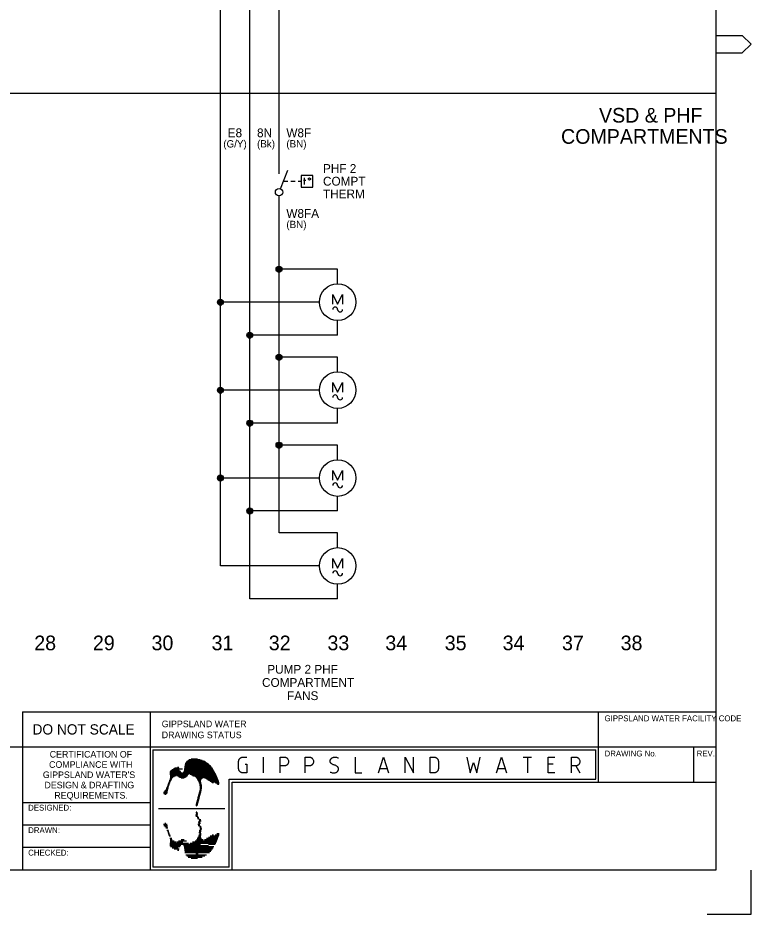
# Model space of a CAD drawing. Extents: x 0 to 841, y 0 to 594.
# Drawn here: x 590.9 to 841, y 0 to 305.7 of the extents above; entities that cross this region are included whole.
import ezdxf

# ---------------------------------------------------------------- set-up
doc = ezdxf.new("R2010")
doc.units = 0
for name, color, linetype in [('A1BORDER', 7, 'Continuous'), ('Level 1', 7, 'Continuous'), ('Level 10', 7, 'Continuous')]:
    doc.layers.add(name, color=color, linetype=linetype)

msp = doc.modelspace()

# ---------------------------------------------------------------- linework, layer by layer
at = {"layer": 'A1BORDER'}
for p, q in [((829, 581), (829, 15)), ((829, 299.76), (838, 299.76)), ((838, 299.76), (841, 296.76)), ((838, 293.76), (841, 296.76)), ((829, 293.76), (838, 293.76)), ((592.5, 69), (592.5, 15)), ((592.5, 69), (829, 69)), ((636, 69), (636, 15)), ((789, 45), (789, 69)), ((28, 57), (829, 57)), ((637, 56), (788, 56)), ((637, 56), (637, 16)), ((788, 46), (788, 56)), ((821.5, 45), (821.5, 57)), ((648.53, 52.12), (654.64, 52.12)), ((648.74, 52.32), (654.24, 52.32)), ((649.02, 52.52), (653.76, 52.52)), ((649.39, 52.72), (653.15, 52.72)), ((650.01, 52.92), (652.2, 52.92)), ((643.04, 48.92), (646.16, 48.92)), ((643.26, 49.12), (645.9, 49.12)), ((643.54, 49.32), (645.57, 49.32)), ((643.85, 49.52), (647.09, 49.52)), ((644.18, 49.72), (645.89, 49.72)), ((644.54, 49.92), (645.36, 49.92)), ((645.37, 50.12), (645.86, 50.12)), ((647.61, 48.92), (657.8, 48.92)), ((647.63, 49.12), (657.68, 49.12)), ((647.66, 49.32), (657.57, 49.32)), ((647.69, 49.52), (657.44, 49.52)), ((647.71, 49.72), (657.31, 49.72)), ((647.75, 49.92), (657.17, 49.92)), ((647.78, 50.12), (657.02, 50.12)), ((647.81, 50.32), (656.86, 50.32)), ((647.85, 50.52), (656.69, 50.52)), ((647.88, 50.72), (656.5, 50.72)), ((647.91, 50.92), (656.3, 50.92)), ((647.96, 51.12), (656.08, 51.12)), ((648.03, 51.32), (655.85, 51.32)), ((648.12, 51.52), (655.59, 51.52)), ((648.23, 51.72), (655.31, 51.72)), ((648.37, 51.92), (655, 51.92)), ((642.72, 45.92), (643.3, 45.92)), ((642.73, 48.12), (658.25, 48.12)), ((642.74, 47.92), (658.35, 47.92)), ((642.75, 48.32), (646.79, 48.32)), ((642.79, 47.72), (649.08, 47.72)), ((642.79, 46.12), (643.4, 46.12)), ((642.81, 48.52), (646.55, 48.52)), ((642.83, 47.52), (648.95, 47.52)), ((642.84, 46.32), (643.5, 46.32)), ((642.85, 47.31), (644.88, 47.31)), ((642.87, 47.12), (644.57, 47.12)), ((642.87, 46.52), (643.6, 46.52)), ((642.88, 46.92), (644.23, 46.92)), ((642.88, 46.72), (643.83, 46.72)), ((642.9, 48.72), (646.37, 48.72)), ((645.14, 47.31), (648.83, 47.31)), ((645.49, 47.12), (648.67, 47.12)), ((645.76, 46.92), (648.42, 46.92)), ((646.05, 46.72), (648.11, 46.72)), ((646.62, 46.52), (647.67, 46.52)), ((647.19, 48.32), (658.14, 48.32)), ((647.42, 48.52), (658.03, 48.52)), ((647.54, 48.72), (657.92, 48.72)), ((649.72, 47.72), (658.45, 47.72)), ((650.12, 47.52), (658.55, 47.52)), ((650.48, 47.31), (658.64, 47.31)), ((650.87, 47.12), (658.73, 47.12)), ((651.36, 46.92), (658.82, 46.92)), ((651.76, 46.72), (658.9, 46.72)), ((651.88, 46.52), (654.15, 46.52)), ((651.99, 46.32), (653.71, 46.32)), ((652.1, 46.12), (653.52, 46.12)), ((652.2, 45.92), (653.4, 45.92)), ((654.57, 46.52), (658.99, 46.52)), ((655, 46.32), (659.07, 46.32)), ((655.31, 46.12), (659.14, 46.12)), ((655.62, 45.92), (659.22, 45.92)), ((663, 46), (788, 46)), ((663, 16), (663, 46)), ((641.55, 42.92), (642.2, 42.92)), ((641.64, 43.12), (642.25, 43.12)), ((641.73, 43.32), (642.3, 43.32)), ((641.82, 43.51), (642.35, 43.51)), ((641.91, 43.72), (642.41, 43.72)), ((641.99, 43.92), (642.48, 43.92)), ((642.06, 44.12), (642.55, 44.12)), ((642.13, 44.32), (642.62, 44.32)), ((642.21, 44.52), (642.69, 44.52)), ((642.28, 44.72), (642.76, 44.72)), ((642.35, 44.92), (642.83, 44.92)), ((642.43, 45.12), (642.9, 45.12)), ((642.5, 45.32), (643, 45.32)), ((642.57, 45.52), (643.1, 45.52)), ((642.65, 45.72), (643.2, 45.72)), ((652.31, 45.72), (653.33, 45.72)), ((652.41, 45.52), (653.31, 45.52)), ((652.5, 45.32), (653.34, 45.32)), ((652.6, 45.12), (653.38, 45.12)), ((652.69, 44.92), (653.41, 44.92)), ((652.78, 44.72), (653.44, 44.72)), ((652.83, 44.52), (653.48, 44.52)), ((652.86, 44.32), (653.53, 44.32)), ((652.89, 44.12), (653.57, 44.12)), ((652.91, 43.92), (653.62, 43.92)), ((652.94, 43.72), (653.67, 43.72)), ((652.97, 43.51), (653.71, 43.51)), ((653, 43.32), (653.69, 43.32)), ((653.02, 43.12), (653.67, 43.12)), ((653.05, 42.92), (653.64, 42.92)), ((655.93, 45.72), (659.29, 45.72)), ((656.24, 45.52), (659.35, 45.52)), ((656.55, 45.32), (659.42, 45.32)), ((656.86, 45.12), (657.74, 45.12)), ((657.17, 44.92), (657.68, 44.92)), ((657.51, 44.72), (657.54, 44.72)), ((657.91, 45.12), (659.48, 45.12)), ((658.19, 44.92), (659.54, 44.92)), ((658.47, 44.72), (659.59, 44.72)), ((658.75, 44.52), (659.58, 44.52)), ((659.02, 44.32), (659.47, 44.32)), ((664, 45), (829, 45)), ((664, 15), (664, 45)), ((640.62, 41.32), (641.88, 41.32)), ((640.63, 41.52), (641.93, 41.52)), ((640.72, 41.12), (641.73, 41.12)), ((640.73, 41.72), (641.95, 41.72)), ((640.9, 41.92), (641.97, 41.92)), ((641.03, 40.92), (641.43, 40.92)), ((641.1, 42.12), (642, 42.12)), ((641.25, 42.31), (642.04, 42.31)), ((641.37, 42.52), (642.09, 42.52)), ((641.46, 42.72), (642.15, 42.72)), ((652.3, 39.92), (652.93, 39.92)), ((652.36, 40.12), (652.99, 40.12)), ((652.41, 40.32), (653.04, 40.32)), ((652.47, 40.52), (653.1, 40.52)), ((652.52, 40.72), (653.15, 40.72)), ((652.57, 40.92), (653.2, 40.92)), ((652.63, 41.12), (653.26, 41.12)), ((652.68, 41.32), (653.31, 41.32)), ((652.74, 41.52), (653.37, 41.52)), ((652.79, 41.72), (653.41, 41.72)), ((652.85, 41.92), (653.45, 41.92)), ((652.9, 42.12), (653.49, 42.12)), ((652.95, 42.31), (653.53, 42.31)), ((652.99, 42.52), (653.57, 42.52)), ((653.03, 42.72), (653.61, 42.72)), ((636, 38), (592.5, 38)), ((651.63, 37.32), (652.23, 37.32)), ((651.64, 37.12), (652.17, 37.12)), ((651.65, 37.52), (652.28, 37.52)), ((651.71, 37.72), (652.34, 37.72)), ((651.76, 37.92), (652.39, 37.92)), ((651.79, 36.92), (651.9, 36.92)), ((651.82, 38.12), (652.44, 38.12)), ((651.87, 38.32), (652.5, 38.32)), ((651.92, 38.52), (652.55, 38.52)), ((651.98, 38.72), (652.61, 38.72)), ((652.03, 38.92), (652.66, 38.92)), ((652.09, 39.12), (652.72, 39.12)), ((652.14, 39.32), (652.77, 39.32)), ((652.2, 39.52), (652.82, 39.52)), ((652.25, 39.72), (652.88, 39.72)), ((638.93, 35.98), (661.47, 35.98)), ((651.54, 33.84), (652.17, 33.84)), ((651.63, 34.64), (652.23, 34.64)), ((651.71, 34.24), (652.34, 34.24)), ((651.79, 35.04), (651.9, 35.04)), ((640.62, 30.64), (641.88, 30.64)), ((641.03, 31.04), (641.43, 31.04)), ((651.65, 33.44), (652.28, 33.44)), ((652.03, 33.04), (652.66, 33.04)), ((652.14, 32.64), (652.77, 32.64)), ((652.34, 30.64), (652.97, 30.64)), ((652.47, 31.44), (653.1, 31.44)), ((652.57, 31.04), (653.2, 31.04)), ((652.66, 32.24), (653.29, 32.24)), ((652.77, 31.84), (653.4, 31.84)), ((636, 30.34), (592.5, 30.34)), ((640.73, 30.24), (641.95, 30.24)), ((641.1, 29.84), (642, 29.84)), ((641.37, 29.44), (642.09, 29.44)), ((641.73, 28.64), (642.3, 28.64)), ((641.91, 28.24), (642.41, 28.24)), ((642.06, 27.84), (642.55, 27.84)), ((652.45, 30.24), (653.07, 30.24)), ((652.66, 27.84), (653.35, 27.84)), ((652.72, 28.24), (653.44, 28.24)), ((652.77, 28.64), (653.46, 28.64)), ((652.9, 29.84), (653.49, 29.84)), ((652.99, 29.44), (653.57, 29.44)), ((653.05, 29.04), (653.64, 29.04)), ((642.21, 27.44), (642.69, 27.44)), ((642.35, 27.04), (642.83, 27.04)), ((642.5, 26.64), (643, 26.64)), ((642.79, 25.84), (643.4, 25.84)), ((642.85, 24.65), (644.88, 24.65)), ((642.87, 25.44), (643.6, 25.44)), ((642.88, 25.04), (644.23, 25.04)), ((645.14, 24.65), (647.18, 24.65)), ((645.76, 25.04), (648.42, 25.04)), ((646.62, 25.44), (647.67, 25.44)), ((650.48, 24.65), (658.64, 24.65)), ((651.36, 25.04), (658.82, 25.04)), ((651.88, 25.44), (654.15, 25.44)), ((652.1, 25.84), (653.52, 25.84)), ((652.31, 26.24), (653.33, 26.24)), ((652.5, 26.64), (653.34, 26.64)), ((652.69, 27.04), (653.41, 27.04)), ((652.83, 27.44), (653.48, 27.44)), ((654.57, 25.44), (658.99, 25.44)), ((655.31, 25.84), (659.14, 25.84)), ((655.93, 26.24), (659.29, 26.24)), ((656.55, 26.64), (659.42, 26.64)), ((657.17, 27.04), (657.68, 27.04)), ((658.19, 27.04), (659.54, 27.04)), ((658.75, 27.44), (659.58, 27.44)), ((636, 22.67), (592.5, 22.67)), ((642.73, 23.84), (653.27, 23.84)), ((642.79, 24.24), (649.08, 24.24)), ((642.81, 23.44), (646.55, 23.44)), ((643.04, 23.04), (646.16, 23.04)), ((643.54, 22.64), (645.57, 22.64)), ((644.18, 22.24), (645.89, 22.24)), ((645.37, 21.84), (645.86, 21.84)), ((647.42, 23.44), (655.89, 23.44)), ((647.61, 23.04), (657.8, 23.04)), ((647.66, 22.64), (657.57, 22.64)), ((647.71, 22.24), (657.31, 22.24)), ((647.78, 21.84), (657.02, 21.84)), ((647.85, 21.44), (656.69, 21.44)), ((649.72, 24.24), (658.45, 24.24)), ((655.94, 23.84), (658.25, 23.84)), ((647.91, 21.04), (656.3, 21.04)), ((648.23, 20.24), (655.31, 20.24)), ((648.53, 19.84), (654.64, 19.84)), ((649.02, 19.44), (653.76, 19.44)), ((650.01, 19.04), (652.2, 19.04)), ((651.57, 20.64), (652.44, 20.64)), ((663, 16), (637, 16)), ((829, 15), (28, 15)), ((829, 15), (829, 15)), ((841, 0), (841, 15)), ((826, 0), (841, 0))]:
    msp.add_line(p, q, dxfattribs=at)
for points in [[(668.49, 51.15), (669.06, 51.15), (669.06, 48.16), (667.64, 48.16), (667.51, 48.16), (667.39, 48.18), (667.28, 48.21), (667.15, 48.25), (667.04, 48.3), (666.93, 48.36), (666.82, 48.43), (666.73, 48.51), (666.64, 48.6), (666.55, 48.7), (666.48, 48.8), (666.41, 48.91), (666.35, 49.02), (666.31, 49.14), (666.27, 49.27), (666.24, 49.39), (666.22, 49.52), (666.22, 49.66), (666.22, 52.05), (666.22, 52.18), (666.24, 52.31), (666.27, 52.43), (666.31, 52.56), (666.35, 52.67), (666.41, 52.79), (666.48, 52.9), (666.55, 53), (666.64, 53.1), (666.73, 53.19), (666.82, 53.27), (666.93, 53.34), (667.04, 53.4), (667.15, 53.45), (667.28, 53.49), (667.39, 53.52), (667.51, 53.54), (667.64, 53.54), (669.06, 53.54)], [(674.74, 48.16), (674.74, 53.54)], [(680.42, 48.16), (680.42, 53.54), (681.84, 53.54), (681.96, 53.54), (682.08, 53.52), (682.2, 53.49), (682.32, 53.45), (682.43, 53.4), (682.54, 53.34), (682.65, 53.27), (682.74, 53.19), (682.84, 53.1), (682.92, 53), (682.99, 52.9), (683.06, 52.79), (683.12, 52.67), (683.17, 52.56), (683.21, 52.43), (683.23, 52.31), (683.25, 52.18), (683.26, 52.05), (683.25, 51.91), (683.23, 51.78), (683.21, 51.66), (683.17, 51.53), (683.12, 51.42), (683.06, 51.3), (682.99, 51.19), (682.92, 51.09), (682.84, 50.99), (682.74, 50.9), (682.65, 50.82), (682.54, 50.75), (682.43, 50.69), (682.32, 50.64), (682.2, 50.6), (682.08, 50.57), (681.96, 50.55), (681.84, 50.55), (680.42, 50.55)], [(688.93, 48.16), (688.93, 53.54), (690.35, 53.54), (690.47, 53.54), (690.59, 53.52), (690.71, 53.49), (690.83, 53.45), (690.94, 53.4), (691.05, 53.34), (691.16, 53.27), (691.26, 53.19), (691.35, 53.1), (691.43, 53), (691.51, 52.9), (691.57, 52.79), (691.63, 52.67), (691.68, 52.56), (691.72, 52.43), (691.75, 52.31), (691.76, 52.18), (691.77, 52.05), (691.76, 51.91), (691.75, 51.78), (691.72, 51.66), (691.68, 51.53), (691.63, 51.42), (691.57, 51.3), (691.51, 51.19), (691.43, 51.09), (691.35, 50.99), (691.26, 50.9), (691.16, 50.82), (691.05, 50.75), (690.94, 50.69), (690.83, 50.64), (690.71, 50.6), (690.59, 50.57), (690.47, 50.55), (690.35, 50.55), (688.93, 50.55)], [(697.45, 48.46), (697.67, 48.36), (697.9, 48.27), (698.12, 48.21), (698.36, 48.17), (698.6, 48.16), (698.84, 48.16), (698.87, 48.16), (699.03, 48.18), (699.18, 48.21), (699.33, 48.26), (699.48, 48.32), (699.62, 48.4), (699.72, 48.46), (699.81, 48.53), (699.9, 48.61), (699.98, 48.69), (700.05, 48.78), (700.11, 48.88), (700.17, 48.99), (700.22, 49.09), (700.25, 49.21), (700.28, 49.32), (700.29, 49.36), (700.3, 49.44), (700.3, 49.52), (700.3, 49.61), (700.29, 49.69), (700.27, 49.77), (700.25, 49.86), (700.22, 49.93), (700.18, 50.01), (700.14, 50.09), (700.09, 50.15), (700.04, 50.21), (700.01, 50.25), (699.85, 50.39), (699.69, 50.51), (699.52, 50.61), (699.34, 50.7), (699.15, 50.78), (698.95, 50.83), (698.87, 50.85), (698.68, 50.9), (698.49, 50.96), (698.3, 51.04), (698.12, 51.14), (697.96, 51.26), (697.8, 51.39), (697.73, 51.45), (697.67, 51.51), (697.62, 51.57), (697.58, 51.64), (697.53, 51.71), (697.5, 51.79), (697.47, 51.87), (697.46, 51.95), (697.44, 52.04), (697.43, 52.12), (697.43, 52.21), (697.44, 52.29), (697.45, 52.35), (697.47, 52.46), (697.51, 52.58), (697.55, 52.69), (697.61, 52.79), (697.67, 52.89), (697.74, 52.99), (697.82, 53.07), (697.9, 53.15), (697.99, 53.23), (698.02, 53.24), (698.15, 53.33), (698.3, 53.4), (698.44, 53.45), (698.6, 53.5), (698.75, 53.52), (698.87, 53.54), (699.11, 53.55), (699.35, 53.53), (699.58, 53.49), (699.82, 53.43), (700.04, 53.35), (700.27, 53.25)], [(705.96, 53.54), (705.96, 48.16), (708.23, 48.16)], [(713.91, 48.16), (715.61, 53.54), (717.32, 48.16)], [(722.99, 48.16), (722.99, 53.54), (725.83, 48.16), (725.83, 53.54)], [(731.52, 48.16), (731.52, 53.54), (732.94, 53.54), (733.06, 53.54), (733.18, 53.52), (733.3, 53.49), (733.42, 53.45), (733.53, 53.4), (733.64, 53.34), (733.75, 53.27), (733.84, 53.19), (733.94, 53.1), (734.02, 53), (734.09, 52.9), (734.16, 52.79), (734.22, 52.67), (734.27, 52.56), (734.31, 52.43), (734.33, 52.31), (734.35, 52.18), (734.36, 52.05), (734.36, 49.66), (734.35, 49.52), (734.33, 49.39), (734.31, 49.27), (734.27, 49.14), (734.22, 49.02), (734.16, 48.91), (734.09, 48.8), (734.02, 48.7), (733.94, 48.6), (733.84, 48.51), (733.75, 48.43), (733.64, 48.36), (733.53, 48.3), (733.42, 48.25), (733.3, 48.21), (733.18, 48.18), (733.06, 48.16), (732.94, 48.16), (731.52, 48.16)], [(744.01, 53.54), (745.14, 48.16), (746.28, 51.75), (747.41, 48.16), (748.55, 53.54)], [(754.22, 48.16), (755.92, 53.54), (757.63, 48.16)], [(763.31, 53.54), (766.15, 53.54)], [(764.73, 53.54), (764.73, 48.16)], [(774.09, 48.16), (771.82, 48.16), (771.82, 53.54), (774.09, 53.54)], [(779.78, 48.16), (779.78, 53.54), (781.2, 53.54), (781.32, 53.54), (781.44, 53.52), (781.56, 53.49), (781.68, 53.45), (781.79, 53.4), (781.9, 53.34), (782.01, 53.27), (782.1, 53.19), (782.2, 53.1), (782.28, 53), (782.35, 52.9), (782.42, 52.79), (782.48, 52.67), (782.53, 52.56), (782.56, 52.43), (782.59, 52.31), (782.61, 52.18), (782.61, 52.05), (782.61, 51.91), (782.59, 51.78), (782.56, 51.66), (782.53, 51.53), (782.48, 51.42), (782.42, 51.3), (782.35, 51.19), (782.28, 51.09), (782.2, 50.99), (782.1, 50.9), (782.01, 50.82), (781.9, 50.75), (781.79, 50.69), (781.68, 50.64), (781.56, 50.6), (781.44, 50.57), (781.32, 50.55), (781.2, 50.55), (779.78, 50.55)], [(714.48, 49.66), (716.75, 49.66)], [(754.79, 49.66), (757.06, 49.66)], [(773.53, 51.15), (771.82, 51.15)], [(781.2, 50.55), (782.61, 48.16)]]:
    msp.add_lwpolyline(points, dxfattribs=at)
at = {"layer": 'Level 1'}
for p, q in [((680, 255), (680, 528.75)), ((670, 107.5), (670, 518.75)), ((660, 118.75), (660, 508.75)), ((28, 280), (829, 280)), ((680, 252.5), (680, 255)), ((680.46, 247.41), (683, 253.75)), ((681.5, 250), (683, 250)), ((684, 250), (685.5, 250)), ((686.5, 250), (687.5, 250)), ((680, 130), (680, 245)), ((700, 220), (680, 220)), ((700, 215), (700, 220)), ((693.75, 208.75), (660, 208.75)), ((700, 197.5), (700, 202.5)), ((700, 197.5), (670, 197.5)), ((700, 190), (680, 190)), ((700, 185), (700, 190)), ((693.75, 178.75), (660, 178.75)), ((700, 167.5), (700, 172.5)), ((700, 167.5), (670, 167.5)), ((700, 160), (680, 160)), ((700, 155), (700, 160)), ((693.75, 148.75), (660, 148.75)), ((700, 137.5), (700, 142.5)), ((700, 137.5), (670, 137.5)), ((700, 130), (680, 130)), ((700, 125), (700, 130)), ((693.75, 118.75), (660, 118.75)), ((700, 107.5), (700, 112.5)), ((700, 107.5), (670, 107.5))]:
    msp.add_line(p, q, dxfattribs=at)
msp.add_lwpolyline([(687.5, 248), (691.5, 248), (691.5, 252), (687.5, 252)], close=True, dxfattribs=at)
for points in [[(688.63, 251.13), (688.63, 248.87)], [(690.36, 250.38), (690.18, 250.42), (690.05, 250.56), (689.99, 250.76), (690.05, 250.94), (690.18, 251.07), (690.36, 251.13), (690.56, 251.07), (690.7, 250.94), (690.74, 250.76), (690.7, 250.56), (690.56, 250.42), (690.36, 250.38)], [(688.38, 250.38), (689.13, 250.38)]]:
    msp.add_lwpolyline(points, dxfattribs=at)
msp.add_circle((680, 246.25), 1.25, dxfattribs=at)
at = {"layer": 'Level 10'}
for p, q in [((679.05, 220.3), (680.95, 220.3)), ((679.2, 220.6), (680.8, 220.6)), ((679.56, 220.9), (680.44, 220.9)), ((680, 221), (680, 221)), ((679, 220), (680.99, 220)), ((679.05, 219.7), (680.95, 219.7)), ((679.2, 219.4), (680.8, 219.4)), ((679.56, 219.1), (680.44, 219.1)), ((698.33, 211.33), (700, 208)), ((698.33, 208), (698.33, 211.33)), ((700, 208), (701.67, 211.33)), ((701.67, 211.33), (701.67, 208)), ((659, 208.75), (660.99, 208.75)), ((659.05, 209.05), (660.95, 209.05)), ((659.05, 208.45), (660.95, 208.45)), ((659.2, 209.35), (660.8, 209.35)), ((659.2, 208.15), (660.8, 208.15)), ((659.56, 209.65), (660.44, 209.65)), ((660, 209.75), (660, 209.75)), ((659.56, 207.85), (660.44, 207.85)), ((669, 197.5), (670.99, 197.5)), ((669.05, 197.8), (670.95, 197.8)), ((669.05, 197.2), (670.95, 197.2)), ((669.2, 198.1), (670.8, 198.1)), ((669.2, 196.9), (670.8, 196.9)), ((669.56, 198.4), (670.44, 198.4)), ((669.56, 196.6), (670.44, 196.6)), ((670, 198.5), (670, 198.5)), ((679, 190), (680.99, 190)), ((679.05, 190.3), (680.95, 190.3)), ((679.05, 189.7), (680.95, 189.7)), ((679.2, 190.6), (680.8, 190.6)), ((679.56, 190.9), (680.44, 190.9)), ((680, 191), (680, 191)), ((679.2, 189.4), (680.8, 189.4)), ((679.56, 189.1), (680.44, 189.1)), ((698.33, 181.33), (700, 178)), ((698.33, 178), (698.33, 181.33)), ((700, 178), (701.67, 181.33)), ((701.67, 181.33), (701.67, 178)), ((659, 178.75), (660.99, 178.75)), ((659.05, 179.05), (660.95, 179.05)), ((659.05, 178.45), (660.95, 178.45)), ((659.2, 179.35), (660.8, 179.35)), ((659.2, 178.15), (660.8, 178.15)), ((659.56, 179.65), (660.44, 179.65)), ((659.56, 177.85), (660.44, 177.85)), ((660, 179.75), (660, 179.75)), ((669.56, 168.4), (670.44, 168.4)), ((670, 168.5), (670, 168.5)), ((669, 167.5), (670.99, 167.5)), ((669.05, 167.8), (670.95, 167.8)), ((669.05, 167.2), (670.95, 167.2)), ((669.2, 168.1), (670.8, 168.1)), ((669.2, 166.9), (670.8, 166.9)), ((669.56, 166.6), (670.44, 166.6)), ((679, 160), (680.99, 160)), ((679.05, 160.3), (680.95, 160.3)), ((679.05, 159.7), (680.95, 159.7)), ((679.2, 160.6), (680.8, 160.6)), ((679.2, 159.4), (680.8, 159.4)), ((679.56, 160.9), (680.44, 160.9)), ((679.56, 159.1), (680.44, 159.1)), ((680, 161), (680, 161)), ((698.33, 151.33), (700, 148)), ((698.33, 148), (698.33, 151.33)), ((700, 148), (701.67, 151.33)), ((701.67, 151.33), (701.67, 148)), ((659, 148.75), (660.99, 148.75)), ((659.05, 149.05), (660.95, 149.05)), ((659.05, 148.45), (660.95, 148.45)), ((659.2, 149.35), (660.8, 149.35)), ((659.2, 148.15), (660.8, 148.15)), ((659.56, 149.65), (660.44, 149.65)), ((659.56, 147.85), (660.44, 147.85)), ((660, 149.75), (660, 149.75)), ((669.05, 137.8), (670.95, 137.8)), ((669.2, 138.1), (670.8, 138.1)), ((669.56, 138.4), (670.44, 138.4)), ((670, 138.5), (670, 138.5)), ((669, 137.5), (670.99, 137.5)), ((669.05, 137.2), (670.95, 137.2)), ((669.2, 136.9), (670.8, 136.9)), ((669.56, 136.6), (670.44, 136.6)), ((698.33, 121.33), (700, 118)), ((698.33, 118), (698.33, 121.33)), ((700, 118), (701.67, 121.33)), ((701.67, 121.33), (701.67, 118))]:
    msp.add_line(p, q, dxfattribs=at)
for centre, radius in [((680, 220), 1), ((700, 208.75), 6.25), ((660, 208.75), 1), ((670, 197.5), 1), ((680, 190), 1), ((700, 178.75), 6.25), ((660, 178.75), 1), ((670, 167.5), 1), ((680, 160), 1), ((700, 148.75), 6.25), ((660, 148.75), 1), ((670, 137.5), 1), ((700, 118.75), 6.25)]:
    msp.add_circle(centre, radius, dxfattribs=at)
for centre, start, end in [((699.17, 206.25), 0, 180), ((700.83, 206.25), 180, 0), ((699.17, 176.25), 0, 180), ((700.83, 176.25), 180, 0), ((699.17, 146.25), 0, 180), ((700.83, 146.25), 180, 0), ((699.17, 116.25), 0, 180), ((700.83, 116.25), 180, 0)]:
    msp.add_arc(centre, 0.83, start, end, dxfattribs=at)

# ---------------------------------------------------------------- texts
at = {"layer": 'A1BORDER'}
for s, height, p in [('GIPPSLAND WATER FACILITY CODE', 1.99998, (791.03, 65.77)), ('DO NOT SCALE', 3.5, (595.92188, 61.25)), ('GIPPSLAND WATER', 2.25, (640, 63.75)), ('DRAWING STATUS', 2.25, (640, 60)), ('CERTIFICATION OF', 2.25, (601.79483, 53.39)), ('DRAWING No.', 1.99998, (791.03, 53.77)), ('REV.', 1.99998, (822.43, 53.77)), ('COMPLIANCE WITH', 2.25, (601.56974, 49.89)), ("GIPPSLAND WATER'S", 2.25, (599.44633, 46.39)), ('DESIGN & DRAFTING', 2.25, (600.00407, 42.89)), ('REQUIREMENTS.', 2.25, (603.3705, 39.39)), ('DESIGNED:', 1.99998, (594.44, 35.29)), ('DRAWN:', 1.99998, (594.44, 27.62)), ('CHECKED:', 1.99998, (594.44, 19.95))]:
    msp.add_text(s, height=height, dxfattribs=at).set_placement(p)
at = {"layer": 'Level 1'}
for s, height, p in [('VSD & PHF', 5, (789.13867, 270)), ('E8', 3, (662.5, 265)), ('8N', 3, (672.5, 265)), ('W8F', 3, (682.5, 265)), ('COMPARTMENTS', 5, (776.18945, 262.76367)), ('(G/Y)', 2.50002, (661, 261.49998)), ('(Bk)', 2.50002, (672.5, 261.49998)), ('(BN)', 2.50002, (682.5, 261.49998)), ('PHF 2', 3, (695, 252.8418)), ('COMPT', 3, (695, 248.5)), ('THERM', 3, (695, 244.1582)), ('W8FA', 3, (682.5, 237.5)), ('(BN)', 2.50002, (682.5, 233.99998)), ('28', 4.99998, (596.52, 90)), ('29', 4.99998, (616.52, 90)), ('30', 4.99998, (636.52, 90)), ('31', 4.99998, (657.01, 90)), ('32', 4.99998, (676.52, 90)), ('33', 4.99998, (696.52, 90)), ('34', 4.99998, (716.26, 90)), ('35', 4.99998, (736.52, 90)), ('34', 4.99998, (756.27098, 90)), ('37', 4.99998, (776.52, 90)), ('38', 4.99998, (796.52, 90)), ('PUMP 2 PHF', 3, (675.99512, 82)), ('COMPARTMENT', 3, (674.20215, 77.5)), ('FANS', 3, (682.71875, 73))]:
    msp.add_text(s, height=height, dxfattribs=at).set_placement(p)

doc.saveas('drawing.dxf')
